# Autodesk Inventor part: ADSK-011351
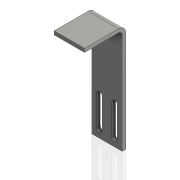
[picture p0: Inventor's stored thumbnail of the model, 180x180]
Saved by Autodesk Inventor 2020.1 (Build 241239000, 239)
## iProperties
Created: 1999-12
Part Number: ADSK-011351
Material: 1.0312 DC05
Document SubType Name: Tôlerie
Designer: sspink
Density: 1 g/cm^3
Sheet Metal Rule: Stahlblech 1.0312 - DC05 -   6.0 mm
Appearance: Stahl
Mass: 64.6777 g
Surface Area: 265.322 cm^2
Volume: 64.6777 cm^3
Flat Pattern Width: 23.5572 cm
Flat Pattern Length: 5 cm
Flat Pattern Area: 117.786 cm^2
Sheet Metal Width: 235,572 mm
Sheet Metal Length: 50,000 mm
Sheet Metal Area: 11778,584 mm^2
Control State: 0
Checked Out: False
Master: False
Shininess: 60.0
Length Units: 11269
Angle Units: 11279
Time Units: 11290
Mass Units: 11283
Length Display Precision: 3
Angle Display Precision: 2
Compacted: True
Cutlength: 9.25
Material Desc: FLAT,HRS,0.250 X 2.00
Material_number: A084333
G_L: 50x235,6 mm
Thickness: 6,000 mm
Dimensions: 50x178x68 mm
Mass: 0,065 kg
Semi finished: Stahlblech 1.0312 - DC05 -   6.0 mm
DocNumber: ADSK-011351.ipt
Folder: 01 - Themengebiete\Simplification\01 - Packaging machine\
VDS_Category: 3D Komponenten
Density: 0.0
Volumn: 0.0
Area: 0.0
PropertySet Name: Model Information
Author: sspink
Revision Number: -
Title: angle
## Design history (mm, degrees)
workplane "Arbeitsebene1"
workplane "Arbeitsebene2"
node "Extrusion2" dims "d10" = 25.4, "d11" = 0
  sketch "Sketch2"
    geometry: L1 (25, -89)-(-25, -89) reference; L2 (-17, -76.5)-(-8, -76.5); L3 (-8, -76.5)-(-8, -26.5); L4 (-8, -26.5)-(-17, -26.5); L5 (-17, -26.5)-(-17, -76.5); L6 (8, -76.5)-(17, -76.5); L7 (17, -76.5)-(17, -26.5); L8 (17, -26.5)-(8, -26.5); L9 (8, -26.5)-(8, -76.5); L10 (12.5, -26.5)-(12.5, -76.5); L11 (-12.5, -26.5)-(-12.5, -76.5); L12 (-12.5, -51.5)-(12.5, -51.5); A1 r 4.5 centre (-12.5, -26.5) between (-8, -26.5) and (-17, -26.5); A2 r 4.5 centre (-12.5, -76.5) between (-17, -76.5) and (-8, -76.5); A3 r 4.5 centre (12.5, -26.5) between (17, -26.5) and (8, -26.5); A4 r 4.5 centre (12.5, -76.5) between (8, -76.5) and (17, -76.5); 2 further points
    constraints: 22 end point, 8 point on circle, 4 centre point, 4 midpoint, 4 parallel, 4 tangent, 3 horizontal, 2 equal length, 2 perpendicular, 2 vertical, 1 vertical alignment
    dimensions: "d23" = 25 distance of L12.start L12.end; "d24" = 12.5 distance between parallel lines of L1 L6; "d25" = 50 distance of L10.start L10.end; "d26" = 9 distance between parallel lines of L9 L7
sketch "Sketch3"
  geometry: L1 (6, 178)-(68, 178); L2 (68, 178)-(68, 172); L3 (68, 172)-(6, 172); L4 (6, 172)-(6, 178)
  constraints: 8 end point, 2 parallel, 1 horizontal, 1 perpendicular
  dimensions: "d12" = 6 distance of L1.end L2.end (= Thickness); "d13" = 62 distance of L2.end L3.end
node "Extrusion3" dims "d14" = 50.8, "d15" = 0
node "Bend1" dims "d18" = 6 (= BendRadius), "d19" = 6 (derived), "d20" = 3 (derived), "d21" = 12 (derived), "d22" = 6 (derived), "SeamGap" = 0.00508, "MinimumRemnant" = 12 (derived), "BendReliefWidth" = 6 (derived)
node "FlatPattern"
node "Solide1"
  node "Extrusion1" dims "d2" = 6 (= Thickness), "d3" = 0
sketch "Sketch1"
  geometry: L1 (25, 89)-(-25, 89); L2 (-25, 89)-(-25, -89); L3 (-25, -89)-(25, -89); L4 (25, -89)-(25, 89); 3 further points
  constraints: 8 end point, 2 midpoint, 2 parallel, 1 horizontal, 1 horizontal alignment, 1 perpendicular, 1 vertical alignment
  dimensions: "d0" = 50 distance of L2.end L3.end; "d1" = 178 distance of L1.end L2.end
node "Corps solides"
node "Corps surfaciques"
feature "Extrusion_mise_à_plat2" dims "d0" = 6 (derived)
other parameters: "Thickness" = 6 (derived), "BendRadius" = 6 (derived), "BendReliefDepth" = 3 (derived), "CornerReliefSize" = 24 (derived), "TransitionRadius" = 6 (derived), "TailleRayonJacobi" = 6 (derived), "TailleJeu" = 6 (derived)
